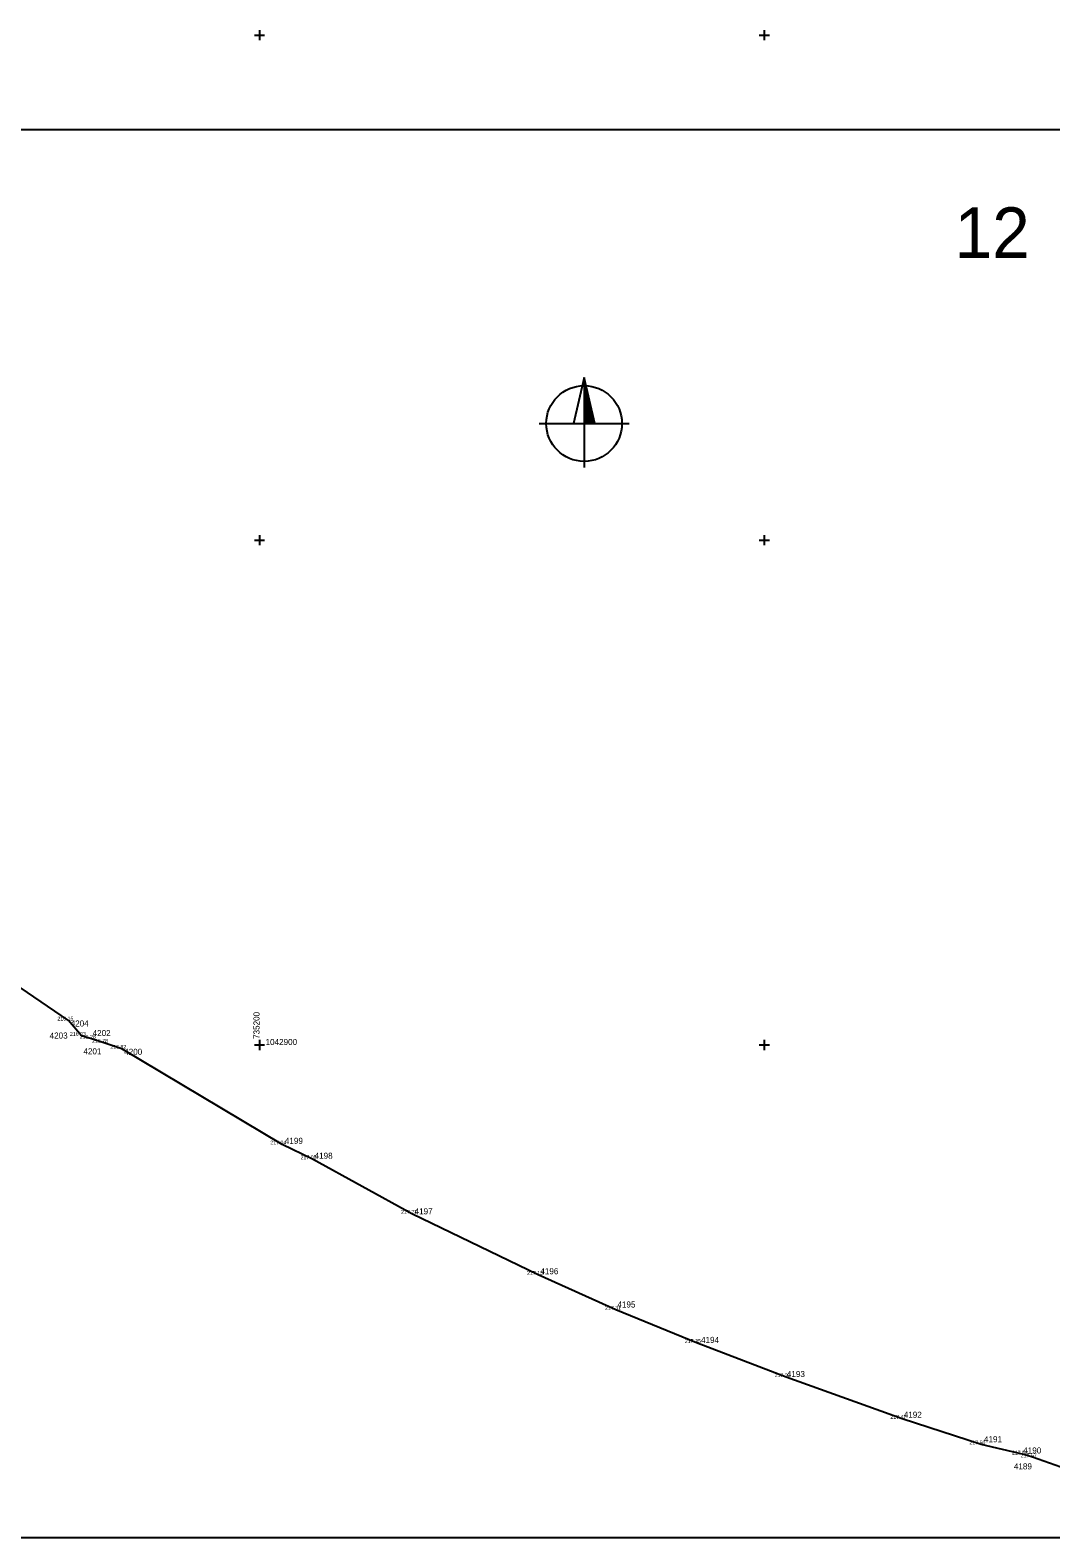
# Model space of a CAD drawing. Extents: x -736532 to -730799, y -1045301 to -1042399.
# Drawn here: x -735245.4 to -735043.2, y -1042997.6 to -1042699 of the extents above; entities that cross this region are included whole.
import ezdxf

# ---------------------------------------------------------------- set-up
doc = ezdxf.new("R2010")
doc.units = 0
for name, color, linetype in [('Vrstva 26', 7, 'Continuous'), ('Vrstva 50', 7, 'Continuous'), ('Vrstva 60', 7, 'Continuous'), ('Vrstva 61', 7, 'Continuous'), ('Vrstva 62', 7, 'Continuous'), ('Vrstva 63', 7, 'Continuous')]:
    doc.layers.add(name, color=color, linetype=linetype)

msp = doc.modelspace()

# ---------------------------------------------------------------- linework, layer by layer
at = {"layer": 'Vrstva 26'}
msp.add_lwpolyline([(-735038.99, -1042984.4), (-735046.86, -1042981.66), (-735048.6, -1042981.12), (-735057.04, -1042979.11), (-735072.71, -1042974.05), (-735095.65, -1042965.77), (-735113.42, -1042959.01), (-735129.43, -1042952.43), (-735144.81, -1042945.52), (-735169.83, -1042933.43), (-735189.53, -1042922.63), (-735195.53, -1042919.69), (-735227.25, -1042900.75), (-735230.86, -1042899.56), (-735233.28, -1042898.77), (-735235.26, -1042898.19), (-735237.85, -1042895.15), (-735261.03, -1042879.38)], dxfattribs=at)
at = {"layer": 'Vrstva 50'}
for p, q in [((-735135.69, -1042767.81), (-735137.81, -1042776.91)), ((-735133.56, -1042776.91), (-735135.69, -1042767.81)), ((-735135.69, -1042767.81), (-735135.69, -1042785.62)), ((-735135.69, -1042768.16), (-735135.6, -1042768.16)), ((-735135.69, -1042768.29), (-735135.57, -1042768.29)), ((-735135.69, -1042768.41), (-735135.55, -1042768.41)), ((-735135.69, -1042768.54), (-735135.52, -1042768.54)), ((-735135.69, -1042768.66), (-735135.49, -1042768.66)), ((-735135.69, -1042768.79), (-735135.46, -1042768.79)), ((-735135.69, -1042768.91), (-735135.43, -1042768.91)), ((-735135.69, -1042769.04), (-735135.4, -1042769.04)), ((-735135.69, -1042769.16), (-735135.37, -1042769.16)), ((-735135.69, -1042769.29), (-735135.34, -1042769.29)), ((-735135.69, -1042769.41), (-735135.31, -1042769.41)), ((-735135.69, -1042769.54), (-735135.28, -1042769.54)), ((-735135.69, -1042769.66), (-735135.25, -1042769.66)), ((-735135.69, -1042769.79), (-735135.22, -1042769.79)), ((-735135.69, -1042769.91), (-735135.19, -1042769.91)), ((-735135.69, -1042770.04), (-735135.17, -1042770.04)), ((-735135.69, -1042770.16), (-735135.14, -1042770.16)), ((-735135.69, -1042770.29), (-735135.11, -1042770.29)), ((-735135.69, -1042770.41), (-735135.08, -1042770.41)), ((-735135.69, -1042770.54), (-735135.05, -1042770.54)), ((-735135.69, -1042770.66), (-735135.02, -1042770.66)), ((-735135.69, -1042770.79), (-735134.99, -1042770.79)), ((-735135.69, -1042770.91), (-735134.96, -1042770.91)), ((-735135.69, -1042771.04), (-735134.93, -1042771.04)), ((-735135.69, -1042771.16), (-735134.9, -1042771.16)), ((-735135.69, -1042771.29), (-735134.87, -1042771.29)), ((-735135.69, -1042771.41), (-735134.84, -1042771.41)), ((-735135.69, -1042771.54), (-735134.82, -1042771.54)), ((-735135.69, -1042771.66), (-735134.79, -1042771.66)), ((-735135.69, -1042771.79), (-735134.76, -1042771.79)), ((-735135.69, -1042771.91), (-735134.73, -1042771.91)), ((-735135.69, -1042772.04), (-735134.7, -1042772.04)), ((-735135.69, -1042772.16), (-735134.67, -1042772.16)), ((-735135.69, -1042772.29), (-735134.64, -1042772.29)), ((-735135.69, -1042772.41), (-735134.61, -1042772.41)), ((-735135.69, -1042772.54), (-735134.58, -1042772.54)), ((-735135.69, -1042772.66), (-735134.55, -1042772.66)), ((-735135.69, -1042772.79), (-735134.52, -1042772.79)), ((-735135.69, -1042772.91), (-735134.49, -1042772.91)), ((-735135.69, -1042773.04), (-735134.46, -1042773.04)), ((-735135.69, -1042773.16), (-735134.44, -1042773.16)), ((-735135.69, -1042773.29), (-735134.41, -1042773.29)), ((-735135.69, -1042773.41), (-735134.38, -1042773.41)), ((-735135.69, -1042773.54), (-735134.35, -1042773.54)), ((-735135.69, -1042773.66), (-735134.32, -1042773.66)), ((-735135.69, -1042773.79), (-735134.29, -1042773.79)), ((-735135.69, -1042773.91), (-735134.26, -1042773.91)), ((-735135.69, -1042774.04), (-735134.23, -1042774.04)), ((-735135.69, -1042774.16), (-735134.2, -1042774.16)), ((-735135.69, -1042774.29), (-735134.17, -1042774.29)), ((-735135.69, -1042774.41), (-735134.14, -1042774.41)), ((-735135.69, -1042774.54), (-735134.11, -1042774.54)), ((-735135.69, -1042774.66), (-735134.08, -1042774.66)), ((-735135.69, -1042774.79), (-735134.06, -1042774.79)), ((-735135.69, -1042774.91), (-735134.03, -1042774.91)), ((-735144.57, -1042776.91), (-735126.8, -1042776.91)), ((-735135.69, -1042775.04), (-735134, -1042775.04)), ((-735135.69, -1042775.16), (-735133.97, -1042775.16)), ((-735135.69, -1042775.29), (-735133.94, -1042775.29)), ((-735135.69, -1042775.41), (-735133.91, -1042775.41)), ((-735135.69, -1042775.54), (-735133.88, -1042775.54)), ((-735135.69, -1042775.66), (-735133.85, -1042775.66)), ((-735135.69, -1042775.79), (-735133.82, -1042775.79)), ((-735135.69, -1042775.91), (-735133.79, -1042775.91)), ((-735135.69, -1042776.04), (-735133.76, -1042776.04)), ((-735135.69, -1042776.16), (-735133.73, -1042776.16)), ((-735135.69, -1042776.29), (-735133.7, -1042776.29)), ((-735135.69, -1042776.41), (-735133.68, -1042776.41)), ((-735135.69, -1042776.54), (-735133.65, -1042776.54)), ((-735135.69, -1042776.66), (-735133.62, -1042776.66)), ((-735135.69, -1042776.79), (-735133.59, -1042776.79))]:
    msp.add_line(p, q, dxfattribs=at)
msp.add_circle((-735135.69, -1042776.91), 7.5, dxfattribs=at)
at = {"layer": 'Vrstva 60'}
for p, q in [((-735237.85, -1042895.15), (-735237.85, -1042895.15)), ((-735235.26, -1042898.19), (-735235.26, -1042898.19)), ((-735233.28, -1042898.77), (-735233.28, -1042898.77)), ((-735230.86, -1042899.56), (-735230.86, -1042899.56)), ((-735227.25, -1042900.75), (-735227.25, -1042900.75)), ((-735195.53, -1042919.69), (-735195.53, -1042919.69)), ((-735189.53, -1042922.63), (-735189.53, -1042922.63)), ((-735169.83, -1042933.43), (-735169.83, -1042933.43)), ((-735144.81, -1042945.52), (-735144.81, -1042945.52)), ((-735129.43, -1042952.43), (-735129.43, -1042952.43)), ((-735113.42, -1042959.01), (-735113.42, -1042959.01)), ((-735095.65, -1042965.77), (-735095.65, -1042965.77)), ((-735072.71, -1042974.05), (-735072.71, -1042974.05)), ((-735057.04, -1042979.11), (-735057.04, -1042979.11)), ((-735048.6, -1042981.12), (-735048.6, -1042981.12)), ((-735046.86, -1042981.66), (-735046.86, -1042981.66))]:
    msp.add_line(p, q, dxfattribs=at)
at = {"layer": 'Vrstva 61'}
for p, q in [((-735201, -1042700), (-735199, -1042700)), ((-735200, -1042699), (-735200, -1042701)), ((-735101, -1042700), (-735099, -1042700)), ((-735100, -1042699), (-735100, -1042701)), ((-735201, -1042800), (-735199, -1042800)), ((-735200, -1042799), (-735200, -1042801)), ((-735101, -1042800), (-735099, -1042800)), ((-735100, -1042799), (-735100, -1042801)), ((-735201, -1042900), (-735199, -1042900)), ((-735200, -1042899), (-735200, -1042901)), ((-735101, -1042900), (-735099, -1042900)), ((-735100, -1042899), (-735100, -1042901))]:
    msp.add_line(p, q, dxfattribs=at)
at = {"layer": 'Vrstva 63'}
msp.add_lwpolyline([(-735436.95, -1042718.65), (-735032.83, -1042718.65), (-735032.83, -1042997.62), (-735436.95, -1042997.62)], close=True, dxfattribs=at)

# ---------------------------------------------------------------- texts
at = {"layer": 'Vrstva 61'}
for s, p in [(' 4204', (-735237.85, -1042896.34)), (' 4202', (-735233.5, -1042898.23)), (' 4203', (-735242.02, -1042898.73)), (' 4201', (-735235.33, -1042901.85)), (' 4200', (-735227.25, -1042901.95)), (' 4199', (-735195.42, -1042919.58)), (' 4198', (-735189.53, -1042922.53)), (' 4197', (-735169.72, -1042933.54)), (' 4196', (-735144.81, -1042945.41)), (' 4195', (-735129.54, -1042952)), (' 4194', (-735112.98, -1042959.01)), (' 4193', (-735095.97, -1042965.77)), (' 4192', (-735072.82, -1042973.83)), (' 4191', (-735056.93, -1042978.68)), (' 4190', (-735049.15, -1042980.91)), (' 4189', (-735051, -1042984.06))]:
    msp.add_text(s, height=1.2, dxfattribs=at).set_placement(p)
at = {"layer": 'Vrstva 62'}
for s, p in [('216 15 ', (-735240.04, -1042895.15)), ('216 03 ', (-735237.56, -1042898.19)), ('216 28 ', (-735235.6, -1042898.77)), ('216 78 ', (-735233.17, -1042899.56)), ('216 82 ', (-735229.56, -1042900.75)), ('217 04 ', (-735197.86, -1042919.69)), ('217 05 ', (-735191.86, -1042922.63)), ('217 21 ', (-735171.95, -1042933.43)), ('217 13 ', (-735147, -1042945.52)), ('217 31 ', (-735131.54, -1042952.43)), ('217 35 ', (-735115.74, -1042959.01)), ('217 33 ', (-735097.95, -1042965.77)), ('217 47 ', (-735075.04, -1042974.05)), ('217 50 ', (-735059.37, -1042979.11)), ('217 58 ', (-735050.94, -1042981.12)), ('217 57 ', (-735049.19, -1042981.66))]:
    msp.add_text(s, height=0.75, dxfattribs=at).set_placement(p)
at = {"layer": 'Vrstva 63'}
for s, height, p in [('12', 10, (-735062.29, -1042744.1)), ('1042900', 1.2, (-735198.8, -1042900))]:
    msp.add_text(s, height=height, dxfattribs=at).set_placement(p)
msp.add_text('735200', height=1.2, rotation=90, dxfattribs=at).set_placement((-735200, -1042898.8))

doc.saveas('drawing.dxf')
